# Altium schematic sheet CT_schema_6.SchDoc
size 364 x 243 mm
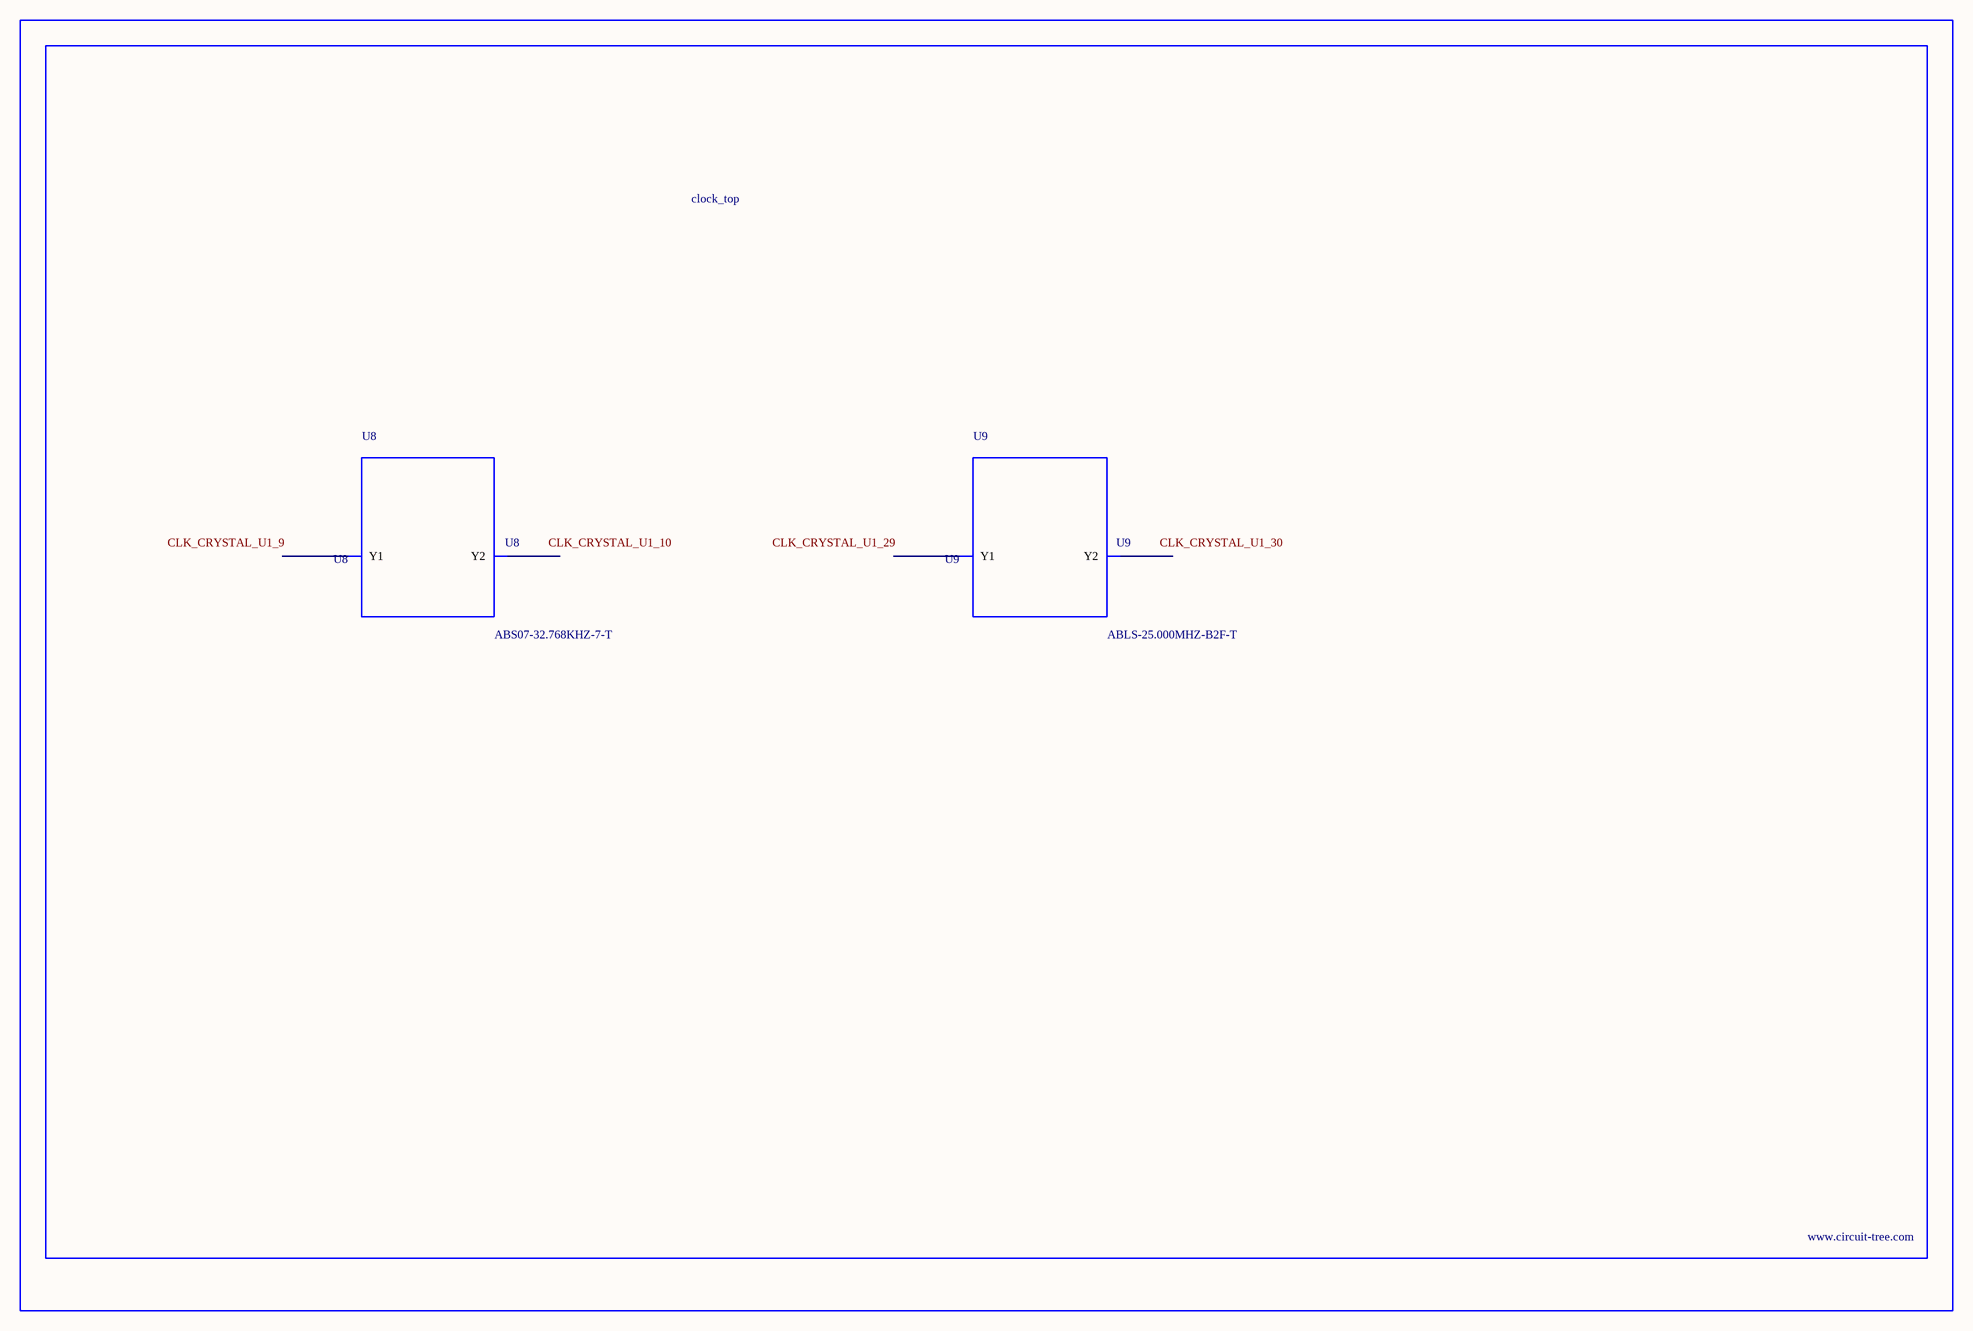
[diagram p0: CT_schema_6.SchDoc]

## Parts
BORDER5  (no value)
U8  ABS07-32.768KHZ-7-T  [ABS07-32.768KHZ-7-T]
U9  ABLS-25.000MHZ-B2F-T  [ABLS-25.000MHZ-B2F-T]

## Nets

Not connected (* = marked no-connect by the designer): U8 1(Y1) 2(Y2); U9 1(Y1) 2(Y2)

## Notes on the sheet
- Labels drawn without touching a wire or pin: CLK_CRYSTAL_U1_9, CLK_CRYSTAL_U1_10, CLK_CRYSTAL_U1_29, CLK_CRYSTAL_U1_30

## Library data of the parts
BORDER5 = BORDER_PAGE5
